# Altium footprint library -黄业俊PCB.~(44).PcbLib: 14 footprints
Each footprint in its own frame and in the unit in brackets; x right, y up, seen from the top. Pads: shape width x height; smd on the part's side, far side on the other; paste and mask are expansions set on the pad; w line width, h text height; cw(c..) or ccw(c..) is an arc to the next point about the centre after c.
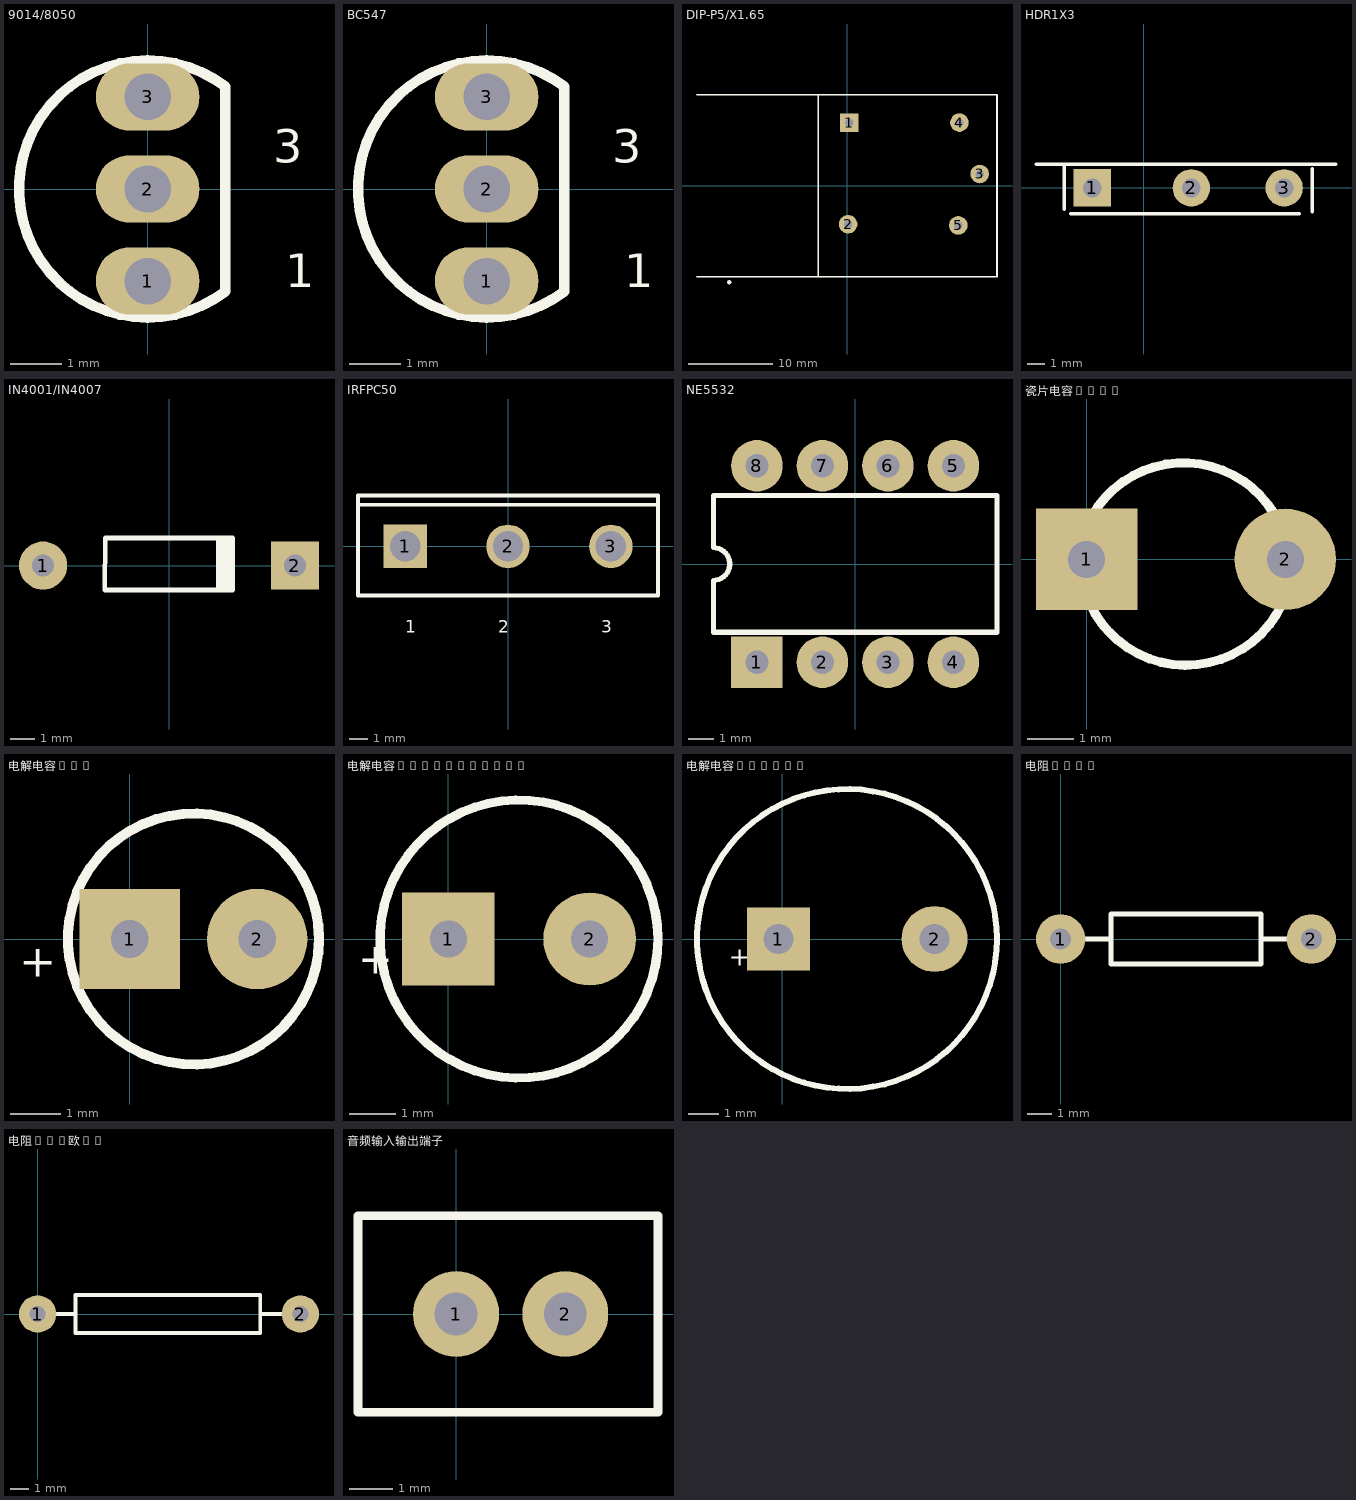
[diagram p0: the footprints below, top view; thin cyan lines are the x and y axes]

## 9014/8050 [mm]
pads (3):
  oval 2x1.3 hole 0.9: 1(0,-1.778) 2(0,0) 3(0,1.778)
Top Overlay:
  lines w0.2: 1.5,-1.98 cw(c0,0) 1.5,1.98 1.5,-1.98
  text "1" at 2.66,-1.9 h0.65
  text "3" at 2.43,0.51 h0.65

## BC547 [mm]
pads (3):
  oval 2x1.3 hole 0.9: 1(0,-1.778) 2(0,0) 3(0,1.778)
Top Overlay:
  lines w0.2: 1.5,-1.98 cw(c0,0) 1.5,1.98 1.5,-1.98
  text "1" at 2.66,-1.9 h0.65
  text "3" at 2.43,0.51 h0.65

## DIP-P5/X1.65 [mm]
pads (5):
  rect 2.2x2.2 hole 1: 1(0.254,7.493)
  round 2.2 hole 1: 2(0.127,-4.572) 3(15.748,1.397) 4(13.335,7.493) 5(13.208,-4.699)
Top Overlay:
  circle w0.25: c-13.97,-11.45 r0.125
  lines w0.2: -17.8,-10.8 17.8,-10.8 17.8,10.8 -17.8,10.8 ; -3.429,-10.795 -3.429,10.805

## HDR1X3 [mm]
pads (3):
  rect 2.2x2.2 hole 1.1: 1(-3.048,0)
  round 2.2 hole 1.1: 2(2.794,0) 3(8.255,0)
Top Overlay:
  lines w0.2: -6.35,1.397 11.303,1.397 ; -4.699,-1.27 -4.699,1.27 ; -4.318,-1.524 9.144,-1.524 ; 9.906,-1.397 9.906,1.143

## IN4001/IN4007 [mm]
pads (2):
  round 2 hole 0.9: 1(-5.23,0)
  rect 2x2 hole 0.9: 2(5.23,0)
Top Overlay:
  rectangle: 1.95,-1.016 2.75,1.143
  lines w0.2: 2.633,-1.016 -2.667,-1.016 -2.65,1.146 2.65,1.146

## IRFPC50 [mm]
pads (3):
  rect 2.3x2.3 hole 1.6: 1(-5.45,0)
  round 2.3 hole 1.6: 2(0,0) 3(5.45,0)
Top Overlay:
  lines w0.2: -7.95,2.2 7.95,2.2 ; -7.95,-2.6 7.95,-2.6 7.95,2.7 -7.95,2.7 -7.95,-2.6
  text "1" at -5.45,-4.575 h0.65
  text "2" at -0.508,-4.575 h0.65
  text "3" at 4.942,-4.575 h0.65

## NE5532 [mm]
pads (8):
  rect 2x2 hole 0.9: 1(-3.81,-3.81)
  round 2 hole 0.9: 2(-1.27,-3.81) 3(1.27,-3.81) 4(3.81,-3.81) 5(3.81,3.81) 6(1.27,3.81) 7(-1.27,3.81) 8(-3.81,3.81)
Top Overlay:
  lines w0.2: -5.5,-2.65 5.5,-2.65 5.5,2.65 -5.5,2.65 -5.5,0.635 cw(c-5.5,0) -5.5,-0.635 -5.5,-2.65

## 瓷片电容C104 [mm]
pads (2):
  rect 2.2x2.2 hole 0.8: 1(0,0)
  round 2.2 hole 0.8: 2(4.318,0)
Top Overlay:
  lines w0.2: 0.052,-0.922 ccw(c2.159,0) 4.251,-0.956 ; 0.116,0.949 cw(c2.108,-0.201) 4.2,0.756

## 电解电容1uf [mm]
pads (2):
  rect 2x2 hole 0.75: 1(0,0)
  round 2 hole 0.75: 2(2.54,0)
Top Overlay:
  circle w0.2: c1.27,0 r2.5
  text "+" at -2.205,-0.75 h0.65

## 电解电容100uf/220uf [mm]
pads (2):
  rect 2x2 hole 0.8: 1(0,0)
  round 2 hole 0.8: 2(3.048,0)
Top Overlay:
  circle w0.2: c1.524,0 r3
  text "+" at -1.951,-0.75 h0.65

## 电解电容1000uf [mm]
pads (2):
  rect 2.1x2.1 hole 1: 1(-0.127,0)
  round 2.2 hole 1: 2(5.08,0)
Top Overlay:
  circle w0.2: c2.159,0 r5
  text "+" at -1.778,-0.889 h0.65

## 电阻1/4W [mm]
pads (2):
  round 2 hole 0.85: 1(0,0) 2(10.16,0)
Top Overlay:
  lines w0.2: 1.016,0 2.032,0 ; 8.128,0 9.144,0 ; 2.032,-1.016 2.032,1.016 8.128,1.016 8.128,-1.016 2.032,-1.016

## 电阻2.2欧1W [mm]
pads (2):
  round 2 hole 0.85: 1(0,0) 2(14.097,0)
Top Overlay:
  lines w0.2: 1.016,0 2.032,0 ; 12.065,0 13.081,0 ; 2.032,-1.016 2.032,1.016 11.938,1.016 11.938,-1.016 2.032,-1.016

## 音频输入输出端子 [mm]
pads (2):
  round 2 hole 1: 1(0,0) 2(2.54,0)
Top Overlay:
  lines w0.2: -2.286,-2.286 4.699,-2.286 4.699,2.286 -2.286,2.286 -2.286,-2.286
